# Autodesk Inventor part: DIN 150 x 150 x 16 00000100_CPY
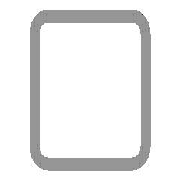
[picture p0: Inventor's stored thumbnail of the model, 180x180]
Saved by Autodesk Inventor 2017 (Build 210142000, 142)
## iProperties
Created: 2016-02
Part Number: DIN 150 x 150 x 16 00000100_CPY
Material: Steel, Mild
Description: Cold formed welded structural hollow sections of non-alloy and fine grain structural steel
Document SubType Name: Modeling
Standard: DIN
Designer: iusti
Standard Revision: 2006-07
Standards Organization: DIN
Language: en-US
Size Designation: 150 x 150 x 16
Categories: <MemberInstance><Categories><Category DisplayName="Structural Shapes" InternalName="089c4875-fa83-4c05-b084-43b9cc11f5ed" Mnemonic="GRDR"><CategoryParameter Dis
Stock Number: 150 x 150 x 16
Mass: 301820 g
Surface Area: 48238.1 cm^2
Volume: 38448.4 cm^3
Density: 7.85 g/cm^3
Appearance: Semi-Polished
IsCustomPart: 1
G_W: 150.000 mm
G_H: 150.000 mm
G_L: 5233.011 mm
+A8523F61-15A1-41A4-8D30-2D7D9D924B11+CUTDETAIL2: Cut
+987C6673-447C-412A-9B24-0CD20188E66E+CUTDETAIL3: Miter 69.88 deg
_CCFamilyMember: 76
_CCFamilyDisplayName: DIN EN 10219-2 (Square Hollow Section - Cold Formed) - Cold formed welded structural hollow sections of non-alloy and fine grain structural steel
_FrameMemberDoc: Frame Member File
_Version: 15.0.0
_GetPNFromCC: 1
Author: iusti
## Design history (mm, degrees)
node "Start plane"
node "End plane"
sketch "Sketch"
  geometry: L1 (-75, -27)-(-75, 27); L2 (-27, 75)-(27, 75); L3 (75, 27)-(75, -27); L4 (27, -75)-(-27, -75); L5 (-27, 59)-(27, 59); L6 (59, 27)-(59, -27); L7 (27, -59)-(-27, -59); L8 (-59, -27)-(-59, 27); L9 (0, 118.918)-(0, -118.918) reference; L10 (-118.918, 0)-(118.918, 0) reference; A1 r 48 centre (-27, -27) between (-75, -27) and (-27, -75); A2 r 48 centre (-27, 27) between (-27, 75) and (-75, 27); A3 r 48 centre (27, 27) between (75, 27) and (27, 75); A4 r 48 centre (27, -27) between (27, -75) and (75, -27); A5 r 32 centre (-27, 27) between (-27, 59) and (-59, 27); A6 r 32 centre (27, 27) between (59, 27) and (27, 59); A7 r 32 centre (27, -27) between (27, -59) and (59, -27); A8 r 32 centre (-27, -27) between (-59, -27) and (-27, -59)
  constraints: 16 end point, 16 point on circle, 8 centre point, 8 tangent, 4 parallel, 3 equal radius, 2 perpendicular, 7 other
  dimensions: "d7" = 48 radius of A1 (= G_IR); "d10" = 150 distance between parallel lines of L2 L4 (= G_H); "d11" = 150 distance between parallel lines of L1 L3 (= G_W); "d12" = 16 distance between parallel lines of L3 L6 (= G_T); "d15" = 75 distance between parallel lines of L2 L10 (= 0.5 x d10); "d16" = 75 distance between parallel lines of L9 L3 (= 0.5 x d11)
extrude "Body" new body sketch "Sketch" stored distance "d3" = 5233.01077 (= G_L); taper "d4" = 0 deg
node "Driven Length"
  sketch "Sketch3"
    geometry: L1 (0, 0)-(10, 0) reference
    constraints: 2 end point, 1 horizontal
  workplane "Work Plane3"
  sketch "Sketch4"
    geometry: L1 (-2, 34.78)-(12, 34.78) reference; L2 (-2, 5267.791)-(12, 5267.791) reference
    dimensions: "d18" = 5233.01077 distance between parallel lines of L1 L2 (derived)
workplane "Work Plane5"
split "Split2"
workplane "Work Plane6"
split "Split3"
body "Solid1"
other parameters: "G_W" = 150 [user parameter; used in 1 equation term], "G_H" = 150 [user parameter; used in 1 equation term], "G_T" = 16 [user parameter; used in 1 equation term], "G_IR" = 48 [user parameter; used in 1 equation term], "G_L" = 5233.01077 (= d18) [user parameter; used in 1 equation term], "G_OFFSET_START" = -34.77977 [user parameter; used in 1 equation term], "G_OFFSET_END" = 27.4779 [user parameter; used in 1 equation term], "d13" = 34.77977 (= -G_OFFSET_START), "d14" = 5267.79054 (= G_OFFSET_END + B_L), "B_L" = 5240.31264 [user parameter; used in 1 equation term], "d17" = 90 deg
